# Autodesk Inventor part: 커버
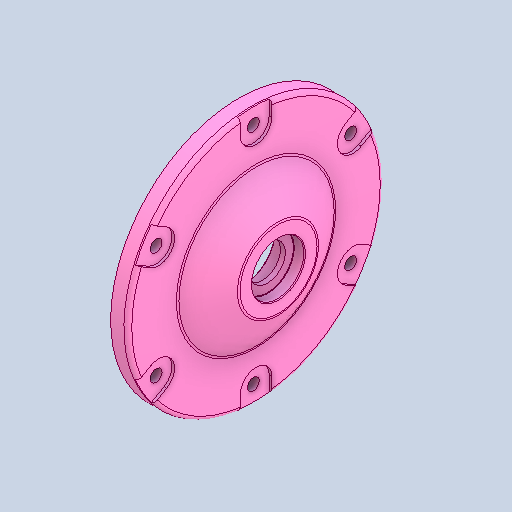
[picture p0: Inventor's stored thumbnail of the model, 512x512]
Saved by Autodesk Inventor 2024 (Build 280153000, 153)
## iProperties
Created: 2025-11
Part Number: 커버
Material: 알루미늄 6061
Document SubType Name: Modeling
Designer: Edu07
Density: 2.7 g/cm^3
Appearance: 기본값
Author: jhkim
Sending System: Autodesk Inventor 2026
Preprocessor: ST-DEVELOPER v20.1
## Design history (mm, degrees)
node "커버1"
node "솔리드2"
node "솔리드1"
